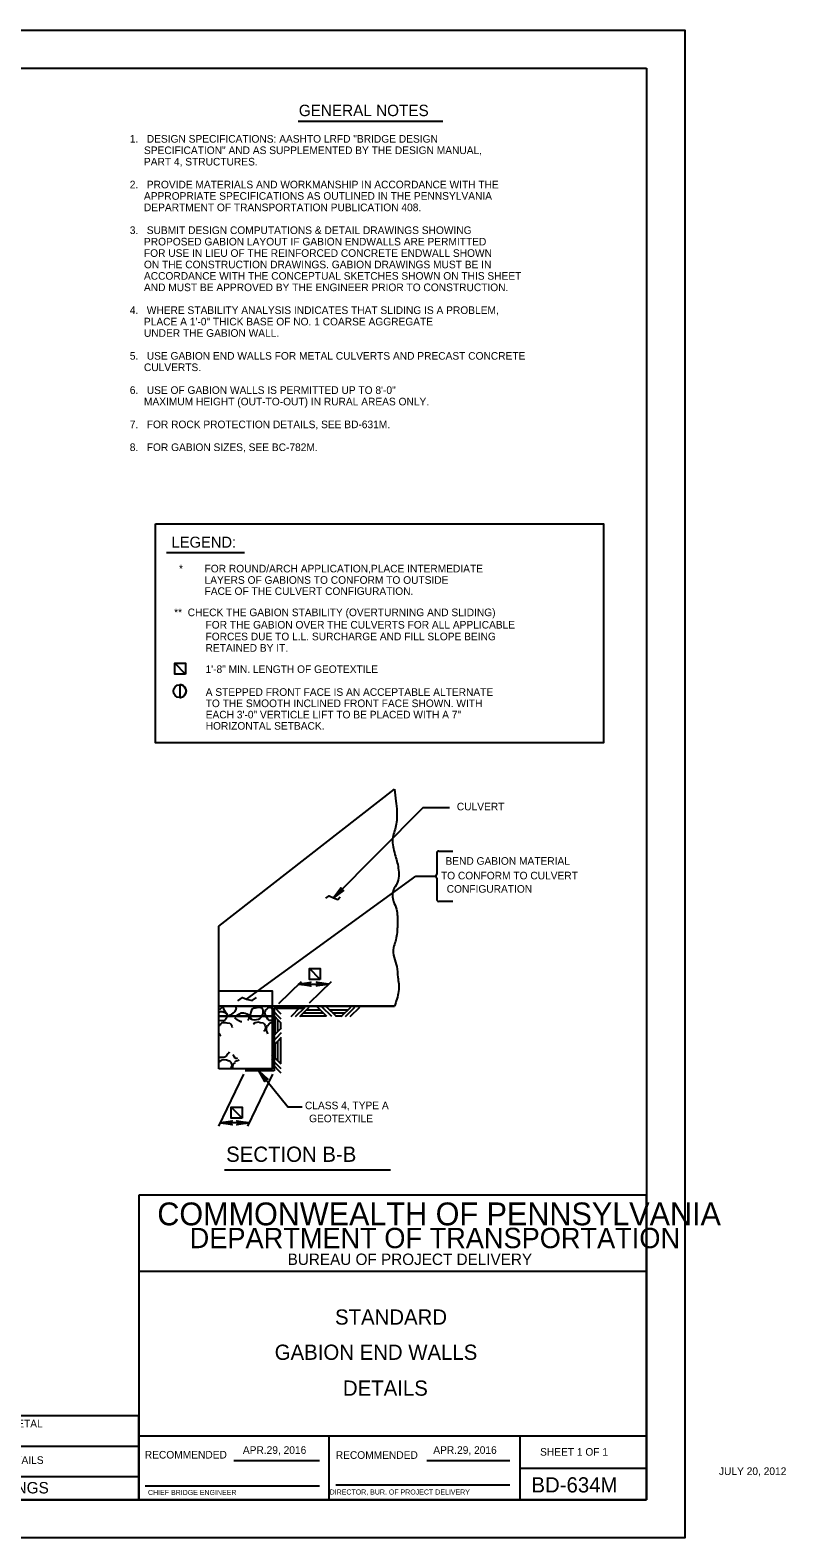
# Model space of a CAD drawing. Extents: x 593 to 1473, y 721 to 1315.
# Drawn here: x 1176 to 1473, y 721 to 1315 of the extents above; entities that cross this region are included whole.
import ezdxf

# ---------------------------------------------------------------- set-up
doc = ezdxf.new("R2010")
doc.units = 0
for name, color, linetype in [('1', 7, 'Continuous'), ('2', 7, 'Continuous'), ('PLT-BNDY', 7, 'Continuous')]:
    doc.layers.add(name, color=color, linetype=linetype)

msp = doc.modelspace()

# ---------------------------------------------------------------- linework, layer by layer
at = {"layer": '1'}
for p, q in [((1237.08, 1061.68), (1232.8, 1065.95)), ((1290.13, 941.43), (1285.86, 945.71)), ((1259.29, 886.81), (1255.02, 891.08))]:
    msp.add_line(p, q, dxfattribs=at)
for points in [[(1225.16, 1120.89), (1401.63, 1120.89), (1401.63, 1034.6), (1225.16, 1034.6)], [(1237.08, 1061.68), (1232.8, 1061.68), (1232.8, 1065.95), (1237.08, 1065.95)], [(1237.08, 1061.68), (1232.8, 1065.95), (1237.08, 1065.95)], [(1234.75, 1057.48), (1234.75, 1052.48), (1235.07, 1052.49), (1235.45, 1052.56), (1235.85, 1052.72), (1236.11, 1052.86), (1236.35, 1053.04), (1236.59, 1053.26), (1236.77, 1053.47), (1237.02, 1053.92), (1237.21, 1054.45), (1237.26, 1055.04), (1237.22, 1055.45), (1237.12, 1055.84), (1236.96, 1056.18), (1236.76, 1056.49), (1236.47, 1056.8), (1236.19, 1057.02), (1235.95, 1057.19), (1235.65, 1057.3), (1235.38, 1057.41), (1235.21, 1057.44), (1235.01, 1057.47)], [(1290.13, 941.43), (1285.86, 941.43), (1285.86, 945.71), (1290.13, 945.71)], [(1290.13, 941.43), (1285.86, 945.71), (1290.13, 945.71)], [(1259.29, 886.81), (1255.02, 886.81), (1255.02, 891.08), (1259.29, 891.08)], [(1259.29, 886.81), (1255.02, 891.08), (1259.29, 891.08)]]:
    msp.add_lwpolyline(points, close=True, dxfattribs=at)
for points in [[(1298.95, 976.44), (1298.6, 976.55), (1295.35, 973.62), (1298.95, 976.44), (1299.26, 976.46), (1295.35, 973.62), (1298.27, 976.87), (1298.16, 977.21), (1295.35, 973.62), (1298.17, 977.54), (1298.16, 977.21)], [(1286.13, 939.01), (1285.96, 939.34), (1281.59, 939.58), (1286.13, 939.01), (1286.36, 938.81), (1281.59, 939.58), (1285.96, 939.8), (1286.12, 940.12), (1281.59, 939.58), (1286.36, 940.34), (1286.12, 940.12)], [(1288.86, 940.15), (1289.03, 939.82), (1293.4, 939.58), (1288.86, 940.15), (1288.63, 940.35), (1293.4, 939.58), (1289.03, 939.37), (1288.88, 939.04), (1293.4, 939.58), (1288.63, 938.82), (1288.88, 939.04)], [(1288.86, 940.15), (1289.03, 939.82), (1293.4, 939.58), (1288.86, 940.15), (1288.63, 940.35), (1293.4, 939.58), (1289.03, 939.37), (1288.88, 939.04), (1293.4, 939.58), (1288.63, 938.82), (1288.88, 939.04)], [(1268.32, 901.48), (1268.47, 901.82), (1265.91, 905.37), (1268.32, 901.48), (1268.31, 901.17), (1265.91, 905.37), (1268.82, 902.11), (1269.17, 902.19), (1265.91, 905.37), (1269.5, 902.13), (1269.17, 902.19)], [(1255.16, 884.32), (1254.99, 884.65), (1250.62, 884.89), (1255.16, 884.32), (1255.39, 884.12), (1250.62, 884.89), (1254.98, 885.11), (1255.14, 885.43), (1250.62, 884.89), (1255.39, 885.65), (1255.14, 885.43)], [(1255.16, 884.32), (1254.99, 884.65), (1250.62, 884.89), (1255.16, 884.32), (1255.39, 884.12), (1250.62, 884.89), (1254.98, 885.11), (1255.14, 885.43), (1250.62, 884.89), (1255.39, 885.65), (1255.14, 885.43)], [(1257.51, 885.46), (1257.68, 885.13), (1262.05, 884.89), (1257.51, 885.46), (1257.28, 885.66), (1262.05, 884.89), (1257.68, 884.67), (1257.53, 884.35), (1262.05, 884.89), (1257.28, 884.13), (1257.53, 884.35)], [(1257.51, 885.46), (1257.68, 885.13), (1262.05, 884.89), (1257.51, 885.46), (1257.28, 885.66), (1262.05, 884.89), (1257.68, 884.67), (1257.53, 884.35), (1262.05, 884.89), (1257.28, 884.13), (1257.53, 884.35)], [(1257.51, 885.46), (1257.68, 885.13), (1262.05, 884.89), (1257.51, 885.46), (1257.28, 885.66), (1262.05, 884.89), (1257.68, 884.67), (1257.53, 884.35), (1262.05, 884.89), (1257.28, 884.13), (1257.53, 884.35)]]:
    msp.add_lwpolyline(points, dxfattribs=at)
msp.add_circle((1234.75, 1054.98), 2.5, dxfattribs=at)
at = {"layer": '2'}
for p, q in [((632.66, 1300.4), (1418.66, 1300.4)), ((1418.66, 1300.4), (1418.66, 736.4)), ((1281.41, 1279.53), (1338.41, 1279.53)), ((1229.53, 1109.64), (1260.28, 1109.64)), ((1234.75, 1057.48), (1234.75, 1052.48)), ((1250.16, 962.37), (1319.35, 1016.37)), ((1330.67, 1009.14), (1295.35, 973.62)), ((1330.67, 1009.14), (1340.96, 1009.14)), ((1336.03, 991.2), (1336.03, 982.83)), ((1336.78, 991.95), (1342.28, 991.95)), ((1261.03, 933.69), (1327.78, 982.08)), ((1327.78, 982.08), (1335.22, 982.08)), ((1336.03, 981.33), (1336.03, 972.95)), ((1336.78, 972.2), (1342.28, 972.2)), ((1250.16, 930.87), (1250.16, 962.37)), ((1273.73, 931.9), (1282.66, 940.63)), ((1281.59, 939.58), (1293.4, 939.58)), ((1285.8, 932.15), (1294.48, 940.63)), ((1274.72, 925.81), (1270.97, 929.56)), ((1271.16, 930.87), (1319.35, 930.87)), ((1319.35, 930.87), (1271.16, 930.87)), ((1274.72, 924.12), (1271.16, 927.87)), ((1274.72, 927.69), (1271.72, 930.87)), ((1271.91, 930.12), (1271.91, 905.37)), ((1271.91, 930.12), (1283.72, 930.12)), ((1278.66, 926.75), (1282.22, 930.5)), ((1280.35, 926.75), (1284.1, 930.5)), ((1282.03, 926.75), (1285.78, 930.5)), ((1292.72, 926.75), (1288.97, 930.5)), ((1294.6, 926.75), (1290.85, 930.5)), ((1296.47, 926.75), (1292.72, 930.5)), ((1298.35, 926.75), (1302.1, 930.5)), ((1300.03, 926.75), (1303.78, 930.5)), ((1301.91, 926.75), (1305.66, 930.5)), ((1274.72, 922.25), (1270.97, 918.5)), ((1274.72, 920.37), (1271.16, 916.62)), ((1274.72, 918.5), (1271.16, 914.75)), ((1274.72, 908), (1270.97, 911.75)), ((1274.72, 906.12), (1270.97, 909.87)), ((1259.82, 904.02), (1249.96, 883.54)), ((1271.16, 906.12), (1250.16, 906.12)), ((1271.91, 905.37), (1260.47, 905.37)), ((1271.26, 904.02), (1261.4, 883.54)), ((1265.91, 905.37), (1277.46, 891.06)), ((1274.72, 904.44), (1271.16, 908.19)), ((1283.03, 891.06), (1277.46, 891.06)), ((1262.05, 884.89), (1250.62, 884.89)), ((1252.41, 866.41), (1317.79, 866.41)), ((1218.66, 856.4), (1218.66, 736.4)), ((1418.66, 856.4), (1218.66, 856.4)), ((1418.66, 736.4), (1418.66, 856.4)), ((1418.66, 826.4), (1218.66, 826.4)), ((1078.03, 769.65), (1218.66, 769.65)), ((1218.66, 736.4), (1218.66, 769.65)), ((1418.66, 761.4), (1218.66, 761.4)), ((1293.66, 736.4), (1293.66, 761.4)), ((1368.66, 761.4), (1368.66, 736.4)), ((1078.03, 757.53), (1218.66, 757.53)), ((1256.12, 751.9), (1289.81, 751.9)), ((1332.1, 751.9), (1364.71, 751.9)), ((1368.66, 748.9), (1418.66, 748.9)), ((1078.03, 745.53), (1218.66, 745.53)), ((1221.16, 741.9), (1289.81, 741.9)), ((1296.28, 742.28), (1364.71, 742.28)), ((1418.66, 736.4), (632.66, 736.4)), ((1078.03, 736.4), (1218.66, 736.4)), ((1218.66, 736.4), (1418.66, 736.4))]:
    msp.add_line(p, q, dxfattribs=at)
for points in [[(1292.35, 973.44), (1293.66, 974.37), (1295.35, 973.62), (1297.03, 972.87), (1297.97, 974)], [(1257.66, 932.94), (1259.53, 934.25), (1261.03, 933.69), (1263.28, 933.12), (1264.97, 934.25)], [(1250.72, 929.75), (1250.35, 929.37)], [(1250.35, 928.62), (1250.53, 928.62)], [(1250.53, 928.62), (1250.72, 928.81)], [(1251.47, 930.5), (1250.72, 929.75)], [(1250.72, 928.81), (1251.47, 928.81)], [(1251.66, 930.87), (1251.47, 930.5)], [(1251.47, 928.81), (1251.85, 928.62)], [(1252.41, 929.19), (1251.85, 930.5)], [(1251.85, 928.62), (1252.6, 928.44)], [(1252.03, 930.69), (1252.03, 930.87)], [(1253.16, 927.87), (1252.41, 929.19)], [(1252.6, 928.44), (1253.16, 928.06)], [(1253.16, 928.06), (1253.35, 927.87)], [(1253.53, 927.31), (1253.16, 927.87)], [(1253.35, 926.75), (1253.16, 926.19)], [(1253.35, 927.87), (1253.35, 927.5)], [(1253.35, 927.5), (1253.35, 926.75)], [(1253.91, 927.12), (1253.53, 927.31)], [(1254.1, 927.12), (1253.91, 927.12)], [(1254.66, 927.31), (1254.1, 927.12)], [(1255.6, 928.06), (1254.66, 927.31)], [(1256.35, 928.62), (1255.6, 928.06)], [(1256.91, 929.56), (1256.35, 928.62)], [(1256.53, 930.87), (1256.91, 930.31)], [(1256.53, 926.56), (1257.1, 927.12)], [(1256.91, 930.31), (1257.1, 929.94)], [(1257.1, 929.94), (1256.91, 929.56)], [(1257.1, 927.12), (1258.03, 927.69)], [(1258.03, 927.69), (1258.97, 928.25)], [(1258.97, 928.25), (1259.35, 928.25)], [(1259.35, 928.25), (1259.91, 928.25)], [(1259.91, 928.25), (1260.47, 928.06)], [(1260.47, 928.06), (1261.22, 927.87)], [(1261.22, 927.87), (1261.78, 927.5)], [(1261.78, 927.5), (1261.97, 927.31)], [(1261.97, 927.31), (1261.97, 926.94)], [(1261.97, 926.94), (1261.97, 926.19)], [(1268.72, 927.12), (1268.16, 928.62)], [(1268.35, 928.62), (1268.72, 929.37)], [(1268.72, 929.37), (1269.1, 929.75)], [(1269.47, 925.81), (1268.72, 927.12)], [(1269.1, 929.75), (1269.47, 930.12)], [(1269.47, 930.12), (1269.85, 930.31)], [(1269.85, 930.31), (1270.22, 930.5)], [(1270.6, 930.31), (1270.22, 930.87)], [(1270.22, 930.5), (1270.41, 930.5)], [(1270.41, 930.5), (1271.16, 930.12)], [(1270.97, 930.12), (1270.6, 930.31)], [(1271.16, 930.12), (1270.97, 930.12)], [(1271.16, 930.12), (1271.16, 930.12)], [(1272.28, 919.62), (1272.28, 926.75)], [(1282.41, 927.12), (1292.35, 927.12)], [(1283.53, 928.25), (1291.22, 928.25)], [(1284.66, 929.37), (1290.1, 929.37)], [(1293.85, 929.37), (1300.97, 929.37)], [(1294.97, 928.25), (1299.85, 928.25)], [(1296.1, 927.12), (1298.72, 927.12)], [(1250.16, 923.19), (1250.35, 923.37)], [(1251.1, 925.06), (1250.35, 925.25)], [(1250.35, 923.37), (1250.72, 923.37)], [(1250.72, 923.56), (1250.91, 923.94)], [(1250.91, 923.94), (1251.28, 924.31)], [(1252.22, 925.06), (1251.1, 925.06)], [(1251.28, 924.31), (1251.85, 924.5)], [(1251.85, 924.5), (1252.78, 924.5)], [(1252.41, 925.25), (1252.22, 925.06)], [(1252.6, 925.44), (1252.41, 925.25)], [(1253.16, 926.19), (1252.6, 925.44)], [(1252.78, 924.5), (1253.35, 924.31)], [(1253.35, 924.31), (1254.47, 924.12)], [(1254.47, 924.12), (1254.85, 923.75)], [(1254.85, 923.75), (1255.03, 923.56)], [(1255.03, 923.56), (1255.22, 923)], [(1255.22, 923), (1255.41, 922.44)], [(1255.41, 922.44), (1255.41, 922.44)], [(1256.72, 926), (1256.53, 926.37)], [(1257.1, 925.62), (1256.72, 926)], [(1258.03, 925.06), (1257.1, 925.62)], [(1258.78, 924.69), (1258.03, 925.06)], [(1259.16, 924.69), (1258.78, 924.69)], [(1261.78, 925.62), (1261.41, 925.25)], [(1261.97, 926.19), (1261.78, 925.62)], [(1263.85, 923.75), (1264.03, 924.12)], [(1263.85, 923.56), (1263.85, 923.56)], [(1264.03, 924.12), (1264.41, 924.5)], [(1264.41, 924.5), (1264.78, 924.5)], [(1264.78, 924.5), (1265.72, 924.69)], [(1265.72, 924.69), (1266.47, 924.5)], [(1266.47, 924.5), (1267.6, 924.31)], [(1267.6, 924.31), (1267.97, 923.94)], [(1268.16, 921.31), (1267.78, 920.94)], [(1267.97, 923.94), (1268.16, 923.75)], [(1268.16, 923.75), (1268.35, 923.19)], [(1268.35, 921.87), (1268.16, 921.31)], [(1268.35, 923.19), (1268.53, 922.62)], [(1268.53, 922.25), (1268.35, 921.87)], [(1268.53, 922.62), (1268.53, 922.25)], [(1268.91, 922.06), (1269.1, 922.62)], [(1268.91, 921.31), (1268.91, 922.06)], [(1269.28, 920.37), (1268.91, 921.31)], [(1269.1, 923), (1269.47, 923.37)], [(1269.1, 922.62), (1269.1, 923)], [(1269.85, 925.25), (1269.47, 925.81)], [(1269.47, 923.37), (1269.85, 923.37)], [(1270.22, 925.25), (1269.85, 925.25)], [(1269.85, 923.56), (1270.03, 923.94)], [(1270.03, 923.94), (1270.41, 924.31)], [(1270.41, 925.25), (1270.22, 925.25)], [(1270.97, 925.25), (1270.41, 925.25)], [(1270.41, 924.31), (1270.78, 924.5)], [(1270.78, 924.5), (1271.16, 924.5)], [(1271.16, 925.44), (1270.97, 925.25)], [(1273.41, 920.75), (1273.41, 925.62)], [(1274.53, 921.87), (1274.53, 924.5)], [(1250.35, 919.81), (1250.16, 920)], [(1250.72, 919.44), (1250.35, 919.81)], [(1251.1, 919.25), (1250.72, 919.44)], [(1269.47, 919.81), (1269.28, 920.37)], [(1272.28, 910.62), (1272.28, 915.87)], [(1273.41, 909.31), (1273.41, 917)], [(1274.53, 908.19), (1274.53, 918.12)], [(1250.35, 910.62), (1250.16, 910.62)], [(1250.91, 910.62), (1250.35, 910.62)], [(1250.53, 908.94), (1250.72, 909.31)], [(1250.72, 909.31), (1251.1, 909.5)], [(1251.47, 910.62), (1250.91, 910.62)], [(1251.1, 909.5), (1251.47, 909.69)], [(1252.03, 910.62), (1251.47, 910.62)], [(1251.47, 909.69), (1252.41, 909.87)], [(1252.41, 910.81), (1252.03, 910.62)], [(1253.16, 911.37), (1252.41, 910.81)], [(1252.41, 909.87), (1253.16, 909.69)], [(1253.72, 912.12), (1253.16, 911.37)], [(1253.16, 909.69), (1254.28, 909.31)], [(1254.1, 912.5), (1253.72, 912.12)], [(1254.28, 912.87), (1254.1, 912.5)], [(1254.28, 909.31), (1254.66, 909.12)], [(1254.66, 909.12), (1254.85, 908.94)], [(1254.85, 908.94), (1255.03, 908.37)], [(1256.16, 911), (1255.6, 911.75)], [(1256.53, 910.44), (1256.16, 911)], [(1256.91, 910.25), (1256.53, 910.44)], [(1256.53, 908.75), (1256.72, 909.12)], [(1256.72, 909.12), (1257.1, 909.31)], [(1257.1, 910.25), (1256.91, 910.25)], [(1257.47, 910.44), (1257.1, 910.25)], [(1257.1, 909.31), (1257.47, 909.5)], [(1257.47, 909.5), (1258.22, 909.69)], [(1250.16, 908.56), (1250.53, 908.75)], [(1254.85, 906.5), (1254.47, 906.12)], [(1255.03, 906.87), (1254.85, 906.5)], [(1255.03, 908.37), (1255.22, 907.81)], [(1255.22, 907.44), (1255.03, 906.87)], [(1255.22, 907.81), (1255.22, 907.44)], [(1255.6, 907.25), (1255.78, 907.81)], [(1255.6, 906.5), (1255.6, 907.25)], [(1255.78, 906.12), (1255.6, 906.5)], [(1255.78, 908), (1256.16, 908.37)], [(1255.78, 907.81), (1255.78, 908)], [(1256.16, 908.37), (1256.53, 908.56)], [(1260.66, 906.12), (1260.66, 905.94)]]:
    msp.add_lwpolyline(points, dxfattribs=at)
for points in [[(1250.16, 930.87), (1250.16, 936.87), (1271.16, 936.87), (1271.16, 930.87)], [(1250.16, 926.94), (1250.16, 930.87), (1271.16, 930.87), (1271.16, 926.94)], [(1250.16, 906.12), (1250.16, 926.94), (1271.16, 926.94), (1271.16, 906.12)]]:
    msp.add_lwpolyline(points, close=True, dxfattribs=at)
for centre, start, end in [((1336.77, 991.19), 90, 180), ((1335.22, 982.83), 270, 360), ((1335.22, 981.28), 0, 90), ((1336.77, 972.93), 180, 270)]:
    msp.add_arc(centre, 0.773, start, end, dxfattribs=at)
for points in [[(1319.35, 1016.37), (1319.91, 1011.69), (1320.28, 1007.56), (1319.91, 1001.94), (1318.6, 996.69), (1319.53, 990.69), (1320.85, 985.25), (1320.28, 979.06), (1318.97, 976.81), (1318.97, 972.12), (1320.1, 969.12), (1320.47, 966.31), (1320.47, 962), (1319.72, 956.37), (1318.97, 953.94), (1319.16, 950), (1320.28, 946.44), (1320.66, 942.31), (1321.03, 939.69), (1320.28, 933.69), (1319.35, 930.87)], [(1263.1, 929.75), (1267.41, 929.75), (1267.41, 927.31), (1265.72, 925.81), (1262.91, 925.81), (1263.1, 929.75)]]:
    msp.add_spline(points, degree=3, dxfattribs=at)
at = {"layer": 'PLT-BNDY'}
msp.add_lwpolyline([(592.66, 1315.4), (1433.66, 1315.4), (1433.66, 721.4), (592.66, 721.4)], close=True, dxfattribs=at)

# ---------------------------------------------------------------- texts
at = {"layer": '2'}
for s, height, p in [('GENERAL NOTES', 4.5, (1281.66, 1281.53)), ('1.   DESIGN SPECIFICATIONS: AASHTO LRFD "BRIDGE DESIGN', 3, (1215.08, 1271.08)), ('     SPECIFICATION" AND AS SUPPLEMENTED BY THE DESIGN MANUAL,', 3, (1215.08, 1266.58)), ('     PART 4, STRUCTURES.', 3, (1215.08, 1262.08)), ('2.   PROVIDE MATERIALS AND WORKMANSHIP IN ACCORDANCE WITH THE', 3, (1215.08, 1253.08)), ('     APPROPRIATE SPECIFICATIONS AS OUTLINED IN THE PENNSYLVANIA', 3, (1215.08, 1248.58)), ('     DEPARTMENT OF TRANSPORTATION PUBLICATION 408.', 3, (1215.08, 1244.08)), ('3.   SUBMIT DESIGN COMPUTATIONS & DETAIL DRAWINGS SHOWING', 3, (1215.08, 1235.08)), ('     PROPOSED GABION LAYOUT IF GABION ENDWALLS ARE PERMITTED', 3, (1215.08, 1230.58)), ('     ON THE CONSTRUCTION DRAWINGS. GABION DRAWINGS MUST BE IN', 3, (1215.08, 1221.58)), ('     FOR USE IN LIEU OF THE REINFORCED CONCRETE ENDWALL SHOWN', 3, (1215.08, 1226.08)), ('     ACCORDANCE WITH THE CONCEPTUAL SKETCHES SHOWN ON THIS SHEET', 3, (1215.08, 1217.08)), ('     AND MUST BE APPROVED BY THE ENGINEER PRIOR TO CONSTRUCTION.', 3, (1215.08, 1212.58)), ('4.   WHERE STABILITY ANALYSIS INDICATES THAT SLIDING IS A PROBLEM,', 3, (1215.08, 1203.58)), ('     PLACE A 1\'-0" THICK BASE OF NO. 1 COARSE AGGREGATE', 3, (1215.08, 1199.08)), ('     UNDER THE GABION WALL.', 3, (1215.08, 1194.58)), ('5.   USE GABION END WALLS FOR METAL CULVERTS AND PRECAST CONCRETE', 3, (1215.08, 1185.58)), ('     CULVERTS.', 3, (1215.08, 1181.08)), ('6.   USE OF GABION WALLS IS PERMITTED UP TO 8\'-0"', 3, (1215.08, 1172.08)), ('     MAXIMUM HEIGHT (OUT-TO-OUT) IN RURAL AREAS ONLY.', 3, (1215.08, 1167.58)), ('7.   FOR ROCK PROTECTION DETAILS, SEE BD-631M.', 3, (1215.08, 1158.58)), ('8.   FOR GABION SIZES, SEE BC-782M.', 3, (1215.08, 1149.58)), ('LEGEND:', 4.331, (1231.53, 1111.52)), ('FOR ROUND/ARCH APPLICATION,PLACE INTERMEDIATE', 3, (1244.53, 1101.77)), ('*', 3, (1234.47, 1101.78)), ('LAYERS OF GABIONS TO CONFORM TO OUTSIDE', 3, (1244.53, 1097.27)), ('FACE OF THE CULVERT CONFIGURATION.', 3, (1244.53, 1092.89)), ('**  CHECK THE GABION STABILITY (OVERTURNING AND SLIDING)', 3, (1232.53, 1084.52)), ('FOR THE GABION OVER THE CULVERTS FOR ALL APPLICABLE ', 3, (1244.91, 1079.64)), ('FORCES DUE TO L.L. SURCHARGE AND FILL SLOPE BEING ', 3, (1244.91, 1075.02)), ('RETAINED BY IT.', 3, (1244.91, 1070.52)), ('1\'-8" MIN. LENGTH OF GEOTEXTILE', 3, (1244.91, 1062.14)), ('A STEPPED FRONT FACE IS AN ACCEPTABLE ALTERNATE', 3, (1244.98, 1053.13)), ('TO THE SMOOTH INCLINED FRONT FACE SHOWN. WITH', 3, (1244.98, 1048.69)), ('EACH 3\'-0" VERTICLE LIFT TO BE PLACED WITH A 7"', 3, (1244.98, 1044.25)), ('HORIZONTAL SETBACK.', 3, (1244.98, 1039.81)), ('CULVERT', 3, (1343.91, 1008.03)), ('BEND GABION MATERIAL ', 3, (1339.41, 986.58)), (' TO CONFORM TO CULVERT', 3, (1336.53, 980.83)), ('CONFIGURATION', 3, (1339.91, 975.58)), ('CLASS 4, TYPE A', 3, (1284.07, 890.26)), ('GEOTEXTILE', 3, (1285.7, 885.13)), ('SECTION B-B', 6, (1253.04, 869.54)), ('COMMONWEALTH OF PENNSYLVANIA', 9, (1225.91, 844.53)), ('DEPARTMENT OF TRANSPORTATION', 8.0002, (1238.66, 835.53)), ('BUREAU OF PROJECT DELIVERY', 4.5, (1277.25, 828.9)), ('STANDARD', 6, (1295.91, 805.4)), ('GABION END WALLS', 6, (1272.16, 791.53)), ('DETAILS', 6, (1299.03, 777.4)), ('END WALL DETAIL FOR METAL ', 3, (1121.03, 764.9)), ('APR.29, 2016', 3, (1259.62, 754.49)), ('APR.29, 2016', 3, (1334.62, 754.49)), ('SHEET 1 OF 1', 3, (1376.7, 753.77)), ('GABION SLOPE WALL DETAILS', 3, (1121.16, 750.53)), ('JULY 20, 2012', 3, (1447.15, 746.16)), ('REFERENCE DRAWINGS', 4.5, (1111.28, 738.9)), ('BD-634M', 6, (1373.28, 739.28)), ('CHIEF BRIDGE ENGINEER', 2.0002, (1222.25, 738.28)), ('   DIRECTOR, BUR. OF PROJECT DELIVERY', 2.0002, (1291.5, 738.46))]:
    msp.add_text(s, height=height, dxfattribs=at).set_placement(p)
for p in [(1220.99, 752.65), (1296.21, 752.53)]:
    msp.add_text('RECOMMENDED', height=3, rotation=360, dxfattribs=at).set_placement(p)

doc.saveas('drawing.dxf')
